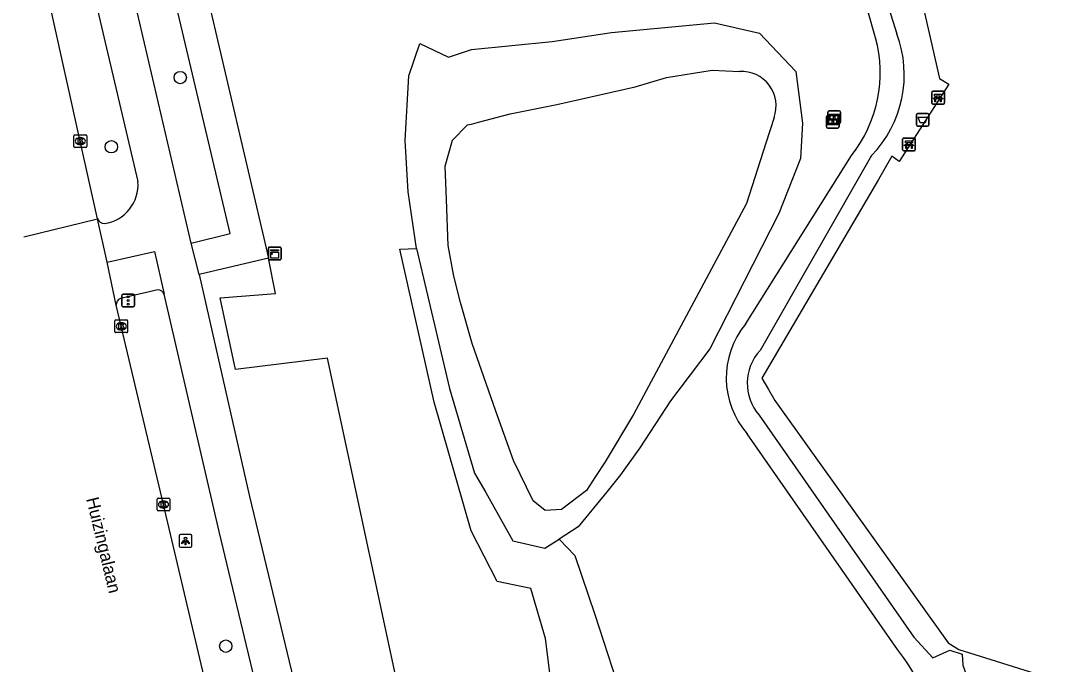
# Model space of a CAD drawing. Extents: x 159451 to 160663, y 388402 to 389723.
# Drawn here: x 159563.1 to 159644.7, y 388629.8 to 388680.5 of the extents above; entities that cross this region are included whole.
import ezdxf

# ---------------------------------------------------------------- set-up
doc = ezdxf.new("R2010")
doc.units = 0
for name, color, linetype in [('IMGEO_Afvalbak', 7, 'Continuous'), ('IMGEO_Bank', 7, 'Continuous'), ('IMGEO_Boom', 7, 'Continuous'), ('IMGEO_Fietspad_gesloten', 7, 'Continuous'), ('IMGEO_Grasland_overig', 7, 'Continuous'), ('IMGEO_Groenvoorziening', 7, 'Continuous'), ('IMGEO_Informatiebord', 7, 'Continuous'), ('IMGEO_Kast', 7, 'Continuous'), ('IMGEO_Kolk', 7, 'Continuous'), ('IMGEO_Lichtpunt', 7, 'Continuous'), ('IMGEO_Meer_plas_ven_vijver', 7, 'Continuous'), ('IMGEO_Openbare_ruimte_label', 7, 'Continuous'), ('IMGEO_Rijbaan_lokaal_halfverhard', 7, 'Continuous'), ('IMGEO_Rijbaan_regionaal_gesloten', 7, 'Continuous'), ('IMGEO_Verkeersregelinstallatiepaal', 7, 'Continuous'), ('IMGEO_Voetpad_open', 7, 'Continuous')]:
    doc.layers.add(name, color=color, linetype=linetype)

msp = doc.modelspace()

# ---------------------------------------------------------------- linework, layer by layer
at = {"layer": 'IMGEO_Afvalbak'}
for p, q in [((159633.667, 388672.309), (159633.667, 388673.109)), ((159633.667, 388673.109), (159633.667, 388672.309)), ((159633.767, 388673.209), (159634.557, 388673.209)), ((159634.557, 388673.209), (159633.767, 388673.209)), ((159634.657, 388673.109), (159634.657, 388672.309)), ((159634.657, 388672.309), (159634.657, 388673.109)), ((159634.557, 388672.209), (159633.767, 388672.209)), ((159633.767, 388672.209), (159634.557, 388672.209))]:
    msp.add_line(p, q, dxfattribs=at)
msp.add_lwpolyline([(159633.81, 388672.923), (159634.514, 388672.923), (159634.365, 388672.453), (159633.959, 388672.453), (159633.81, 388672.923)], dxfattribs=at)
for centre, start, end in [((159633.767, 388673.109), 90, 180), ((159633.767, 388673.109), 90, 180), ((159634.557, 388673.109), 0, 90), ((159634.557, 388673.109), 360, 90), ((159633.767, 388672.309), 180, 270), ((159633.767, 388672.309), 180, 270), ((159634.557, 388672.309), 270, 0), ((159634.557, 388672.309), 270, 0)]:
    msp.add_arc(centre, 0.1, start, end, dxfattribs=at)
at = {"layer": 'IMGEO_Bank'}
for p, q in [((159634.953, 388674.946), (159635.794, 388674.946)), ((159635.794, 388674.946), (159634.953, 388674.946)), ((159634.878, 388674.021), (159634.878, 388674.862)), ((159634.878, 388674.862), (159634.878, 388674.021)), ((159635.575, 388674.344), (159635.182, 388674.344)), ((159635.187, 388674.452), (159635.187, 388674.558)), ((159635.231, 388674.558), (159635.231, 388674.452)), ((159635.519, 388674.564), (159635.237, 388674.564)), ((159635.237, 388674.446), (159635.519, 388674.446)), ((159635.525, 388674.452), (159635.525, 388674.558)), ((159635.569, 388674.558), (159635.569, 388674.452)), ((159635.878, 388674.871), (159635.878, 388674.03)), ((159635.878, 388674.03), (159635.878, 388674.871)), ((159635.803, 388673.946), (159634.962, 388673.946)), ((159634.962, 388673.946), (159635.803, 388673.946)), ((159632.587, 388670.343), (159632.587, 388671.184)), ((159632.587, 388671.184), (159632.587, 388670.343)), ((159632.662, 388671.268), (159633.503, 388671.268)), ((159633.503, 388671.268), (159632.662, 388671.268)), ((159632.896, 388670.774), (159632.896, 388670.88)), ((159632.94, 388670.88), (159632.94, 388670.774)), ((159633.228, 388670.886), (159632.946, 388670.886)), ((159633.234, 388670.774), (159633.234, 388670.88)), ((159633.278, 388670.88), (159633.278, 388670.774)), ((159633.587, 388671.193), (159633.587, 388670.352)), ((159633.587, 388670.352), (159633.587, 388671.193)), ((159633.512, 388670.268), (159632.671, 388670.268)), ((159632.671, 388670.268), (159633.512, 388670.268)), ((159633.284, 388670.666), (159632.891, 388670.666)), ((159632.946, 388670.768), (159633.228, 388670.768))]:
    msp.add_line(p, q, dxfattribs=at)
for points in [[(159635.125, 388674.344), (159634.983, 388674.344), (159635.095, 388674.446), (159635.181, 388674.446)], [(159635.181, 388674.564), (159635.095, 388674.564), (159635.095, 388674.725), (159635.658, 388674.725), (159635.658, 388674.564), (159635.575, 388674.564)], [(159635.175, 388674.337), (159635.175, 388674.13), (159635.132, 388674.13), (159635.132, 388674.337)], [(159635.575, 388674.446), (159635.658, 388674.446), (159635.77, 388674.344), (159635.631, 388674.344)], [(159635.625, 388674.337), (159635.625, 388674.13), (159635.581, 388674.13), (159635.581, 388674.337)], [(159632.89, 388670.886), (159632.804, 388670.886), (159632.804, 388671.047), (159633.367, 388671.047), (159633.367, 388670.886), (159633.284, 388670.886)], [(159632.834, 388670.666), (159632.692, 388670.666), (159632.804, 388670.768), (159632.89, 388670.768)], [(159632.884, 388670.659), (159632.884, 388670.452), (159632.841, 388670.452), (159632.841, 388670.659)], [(159633.284, 388670.768), (159633.367, 388670.768), (159633.479, 388670.666), (159633.34, 388670.666)], [(159633.334, 388670.659), (159633.334, 388670.452), (159633.29, 388670.452), (159633.29, 388670.659)]]:
    msp.add_lwpolyline(points, dxfattribs=at)
for centre, radius, start, end in [((159634.956, 388674.868), 0.0779, 92.4484, 184.28452), ((159634.956, 388674.868), 0.0779, 92.4484, 184.28452), ((159635.8, 388674.868), 0.0779, 2.4484, 94.28452), ((159635.8, 388674.868), 0.0779, 2.4484, 94.28452), ((159635.125, 388674.337), 0.00671, 2.89567, 87.10433), ((159635.182, 388674.337), 0.00671, 92.89567, 177.10433), ((159635.18, 388674.557), 0.00671, 2.89567, 87.10433), ((159635.18, 388674.453), 0.00671, 272.89567, 357.10433), ((159635.237, 388674.557), 0.00671, 92.89567, 177.10433), ((159635.237, 388674.453), 0.00671, 182.89567, 267.10433), ((159635.519, 388674.557), 0.00671, 2.89567, 87.10433), ((159635.519, 388674.453), 0.00671, 272.89567, 357.10433), ((159635.576, 388674.557), 0.00671, 92.89567, 177.10433), ((159635.576, 388674.453), 0.00671, 182.89567, 267.10433), ((159635.574, 388674.337), 0.00671, 2.89567, 87.10433), ((159635.631, 388674.337), 0.00671, 92.89567, 177.10433), ((159634.956, 388674.024), 0.0779, 182.4484, 274.28452), ((159634.956, 388674.024), 0.0779, 182.4484, 274.28452), ((159635.8, 388674.024), 0.0779, 272.4484, 4.28452), ((159635.8, 388674.024), 0.0779, 272.4484, 4.28452), ((159632.665, 388671.19), 0.0779, 92.4484, 184.28452), ((159632.665, 388671.19), 0.0779, 92.4484, 184.28452), ((159632.889, 388670.879), 0.00671, 2.89567, 87.10433), ((159632.946, 388670.879), 0.00671, 92.89567, 177.10433), ((159633.228, 388670.879), 0.00671, 2.89567, 87.10433), ((159633.285, 388670.879), 0.00671, 92.89567, 177.10433), ((159633.509, 388671.19), 0.0779, 2.4484, 94.28452), ((159633.509, 388671.19), 0.0779, 2.4484, 94.28452), ((159632.665, 388670.346), 0.0779, 182.4484, 274.28452), ((159632.665, 388670.346), 0.0779, 182.4484, 274.28452), ((159632.834, 388670.659), 0.00671, 2.89567, 87.10433), ((159632.891, 388670.659), 0.00671, 92.89567, 177.10433), ((159632.889, 388670.775), 0.00671, 272.89567, 357.10433), ((159632.946, 388670.775), 0.00671, 182.89567, 267.10433), ((159633.228, 388670.775), 0.00671, 272.89567, 357.10433), ((159633.285, 388670.775), 0.00671, 182.89567, 267.10433), ((159633.283, 388670.659), 0.00671, 2.89567, 87.10433), ((159633.34, 388670.659), 0.00671, 92.89567, 177.10433), ((159633.509, 388670.346), 0.0779, 272.4484, 4.28452), ((159633.509, 388670.346), 0.0779, 272.4484, 4.28452)]:
    msp.add_arc(centre, radius, start, end, dxfattribs=at)
at = {"layer": 'IMGEO_Boom'}
for centre in [(159575.671, 388676.03), (159570.243, 388670.579), (159579.258, 388631.237)]:
    msp.add_circle(centre, 0.489, dxfattribs=at)
at = {"layer": 'IMGEO_Fietspad_gesloten'}
for points in [[(159576.544, 388662.982), (159568.624, 388696.886)], [(159566.996, 388690.549), (159572.338, 388667.842)], [(159577.172, 388660.52), (159576.544, 388662.982)], [(159569.913, 388661.5), (159573.643, 388662.34), (159574.415, 388658.968)], [(159577.172, 388660.52), (159581.133, 388643.019), (159589.369, 388608.734), (159590.61, 388603.644), (159594.52, 388587.297), (159598.928, 388568.512), (159603.765, 388547.95), (159608.335, 388528.706), (159613.26, 388507.823), (159617.766, 388488.657), (159622.428, 388468.978), (159626.817, 388450.4), (159631.399, 388431.147), (159636.049, 388411.652), (159638.028, 388403.254)], [(159635.066, 388402.93), (159633.14, 388411.125), (159628.643, 388429.97), (159623.96, 388449.846), (159619.346, 388469.16), (159614.917, 388487.946), (159610.308, 388507.337), (159605.503, 388527.843), (159601.008, 388546.724), (159596.625, 388565.41), (159591.677, 388586.33), (159588.042, 388601.633), (159586.471, 388608.09), (159578.73, 388640.269), (159574.415, 388658.968)]]:
    msp.add_lwpolyline(points, dxfattribs=at)
for centre, radius, start, end in [((159569.262, 388667.587), 3.086, 277.89338, 4.73639), ((159569.684, 388665.092), 0.562, 201.15545, 270.21674)]:
    msp.add_arc(centre, radius, start, end, dxfattribs=at)
at = {"layer": 'IMGEO_Grasland_overig'}
msp.add_lwpolyline([(159633.097, 388708.327), (159629.533, 388707.486), (159628.247, 388706.879), (159633.92, 388682.9), (159635.485, 388675.951), (159636.218, 388675.518), (159632.325, 388669.408), (159631.738, 388669.831), (159630.685, 388668.011), (159622.022, 388653.255), (159621.504, 388652.358), (159622.015, 388651.458), (159622.52, 388650.598), (159636.167, 388631.494), (159637.02, 388630.984), (159656.572, 388624.863)], dxfattribs=at)
at = {"layer": 'IMGEO_Groenvoorziening'}
for points in [[(159594.279, 388662.568), (159593.625, 388667.034), (159593.386, 388671.081), (159593.685, 388676.178), (159594.552, 388678.721), (159596.819, 388677.646), (159598.608, 388678.239), (159604.972, 388678.878), (159609.651, 388679.568), (159617.774, 388680.34), (159621.302, 388679.529), (159624.173, 388676.496), (159624.703, 388672.434), (159624.546, 388669.663), (159622.821, 388665.329), (159617.4, 388654.671), (159614.286, 388650.567), (159611.88, 388646.851), (159610.362, 388644.744), (159609.304, 388643.418), (159607.035, 388640.645), (159605.526, 388639.679)], [(159617.133, 388567.112), (159614.295, 388579.867), (159611.298, 388593.777), (159608.357, 388609.407), (159606.398, 388618.373), (159605.048, 388627.034), (159604.46, 388631.854), (159603.293, 388635.791), (159600.643, 388636.335), (159598.603, 388640.324), (159595.684, 388650.454), (159592.966, 388662.518), (159594.279, 388662.568)], [(159594.279, 388662.568), (159596.889, 388651.549), (159598.856, 388644.869), (159599.755, 388643.337), (159601.866, 388639.544), (159604.405, 388638.962), (159605.526, 388639.679)], [(159635.077, 388466.751), (159631.299, 388467.946), (159607.055, 388561.755), (159587.271, 388653.938), (159580.037, 388653.046), (159578.816, 388658.684), (159583.172, 388659.02), (159582.628, 388661.796)], [(159605.526, 388639.679), (159606.749, 388638.389), (159608.339, 388633.739), (159610.052, 388628.478), (159611.363, 388621.757), (159612.902, 388604.641), (159614.422, 388593.149), (159615.567, 388584.134), (159616.974, 388575.645)]]:
    msp.add_lwpolyline(points, dxfattribs=at)
at = {"layer": 'IMGEO_Informatiebord'}
for p, q in [((159626.695, 388672.513), (159626.695, 388673.313)), ((159626.695, 388673.313), (159626.695, 388672.513)), ((159626.795, 388673.413), (159627.585, 388673.413)), ((159627.585, 388673.413), (159626.795, 388673.413)), ((159627.685, 388673.313), (159627.685, 388672.513)), ((159627.685, 388672.513), (159627.685, 388673.313)), ((159626.584, 388672.145), (159626.584, 388672.945)), ((159626.584, 388672.945), (159626.584, 388672.145)), ((159626.684, 388673.045), (159627.474, 388673.045)), ((159627.474, 388673.045), (159626.684, 388673.045)), ((159627.574, 388672.945), (159627.574, 388672.145)), ((159627.574, 388672.145), (159627.574, 388672.945)), ((159627.474, 388672.045), (159626.684, 388672.045)), ((159626.684, 388672.045), (159627.474, 388672.045)), ((159627.585, 388672.413), (159626.795, 388672.413)), ((159626.795, 388672.413), (159627.585, 388672.413))]:
    msp.add_line(p, q, dxfattribs=at)
for points in [[(159626.685, 388672.777), (159627.473, 388672.777), (159627.473, 388672.313), (159626.685, 388672.313), (159626.685, 388672.777)], [(159626.75, 388672.712), (159626.75, 388672.378), (159627.025, 388672.378), (159627.026, 388672.591), (159627.13, 388672.592), (159627.131, 388672.378), (159627.408, 388672.378), (159627.408, 388672.712), (159627.132, 388672.712), (159627.132, 388672.632), (159627.026, 388672.632), (159627.026, 388672.712), (159626.75, 388672.712)], [(159626.796, 388673.145), (159627.584, 388673.145), (159627.584, 388672.681), (159626.796, 388672.681), (159626.796, 388673.145)], [(159626.861, 388673.08), (159626.861, 388672.746), (159627.136, 388672.746), (159627.137, 388672.959), (159627.241, 388672.96), (159627.242, 388672.746), (159627.519, 388672.746), (159627.519, 388673.08), (159627.243, 388673.08), (159627.243, 388673), (159627.137, 388673), (159627.137, 388673.08), (159626.861, 388673.08)]]:
    msp.add_lwpolyline(points, dxfattribs=at)
for centre, start, end in [((159626.795, 388673.313), 90, 180), ((159626.795, 388673.313), 90, 180), ((159627.585, 388673.313), 0, 90), ((159627.585, 388673.313), 360, 90), ((159626.684, 388672.945), 90, 180), ((159626.684, 388672.945), 90, 180), ((159626.795, 388672.513), 180, 270), ((159626.795, 388672.513), 180, 270), ((159627.474, 388672.945), 0, 90), ((159627.474, 388672.945), 360, 90), ((159627.585, 388672.513), 270, 0), ((159627.585, 388672.513), 270, 0), ((159626.684, 388672.145), 180, 270), ((159626.684, 388672.145), 180, 270), ((159627.474, 388672.145), 270, 0), ((159627.474, 388672.145), 270, 0)]:
    msp.add_arc(centre, 0.1, start, end, dxfattribs=at)
at = {"layer": 'IMGEO_Kast'}
for p, q in [((159582.613, 388661.743), (159582.613, 388662.584)), ((159582.613, 388662.584), (159582.613, 388661.743)), ((159582.688, 388662.668), (159583.529, 388662.668)), ((159583.529, 388662.668), (159582.688, 388662.668)), ((159583.613, 388662.593), (159583.613, 388661.752)), ((159583.613, 388661.752), (159583.613, 388662.593)), ((159583.538, 388661.668), (159582.697, 388661.668)), ((159582.697, 388661.668), (159583.538, 388661.668))]:
    msp.add_line(p, q, dxfattribs=at)
for points in [[(159582.808, 388662.458), (159583.408, 388662.458), (159583.408, 388662.373), (159582.808, 388662.373), (159582.808, 388662.458)], [(159582.808, 388662.283), (159583.408, 388662.283), (159583.408, 388661.794), (159582.808, 388661.794), (159582.808, 388662.283)]]:
    msp.add_lwpolyline(points, dxfattribs=at)
msp.add_circle((159582.892, 388662.132), 0.0377, dxfattribs=at)
for centre, start, end in [((159582.691, 388662.59), 92.4484, 184.28452), ((159582.691, 388662.59), 92.4484, 184.28452), ((159583.535, 388662.59), 2.4484, 94.28452), ((159583.535, 388662.59), 2.4484, 94.28452), ((159582.691, 388661.746), 182.4484, 274.28452), ((159582.691, 388661.746), 182.4484, 274.28452), ((159583.535, 388661.746), 272.4484, 4.28452), ((159583.535, 388661.746), 272.4484, 4.28452)]:
    msp.add_arc(centre, 0.0779, start, end, dxfattribs=at)
at = {"layer": 'IMGEO_Kolk'}
for p, q in [((159567.297, 388670.598), (159567.297, 388671.45)), ((159567.372, 388671.524), (159568.224, 388671.524)), ((159567.785, 388671.304), (159567.81, 388671.304)), ((159568.298, 388671.45), (159568.298, 388670.598)), ((159568.224, 388670.524), (159567.372, 388670.524)), ((159567.808, 388670.744), (159567.783, 388670.744)), ((159570.523, 388656.012), (159570.523, 388656.864)), ((159570.598, 388656.938), (159571.45, 388656.938)), ((159571.034, 388656.158), (159571.009, 388656.158)), ((159571.011, 388656.718), (159571.036, 388656.718)), ((159571.524, 388656.864), (159571.524, 388656.012)), ((159571.45, 388655.938), (159570.598, 388655.938)), ((159573.85, 388641.975), (159573.85, 388642.827)), ((159573.925, 388642.901), (159574.777, 388642.901)), ((159574.338, 388642.681), (159574.363, 388642.681)), ((159574.851, 388642.827), (159574.851, 388641.975)), ((159574.777, 388641.901), (159573.925, 388641.901)), ((159574.361, 388642.121), (159574.336, 388642.121))]:
    msp.add_line(p, q, dxfattribs=at)
for points in [[(159567.297, 388670.598), (159567.297, 388671.45)], [(159567.372, 388671.524), (159568.224, 388671.524)], [(159567.618, 388671.224), (159567.741, 388671.224), (159567.741, 388671.073), (159567.871, 388671.224), (159568.035, 388671.224), (159567.889, 388671.073), (159568.042, 388670.824), (159567.89, 388670.824), (159567.805, 388670.988), (159567.741, 388670.921), (159567.741, 388670.824), (159567.618, 388670.824), (159567.618, 388671.224)], [(159568.298, 388671.45), (159568.298, 388670.598)], [(159568.224, 388670.524), (159567.372, 388670.524)], [(159570.523, 388656.012), (159570.523, 388656.864)], [(159570.598, 388656.938), (159571.45, 388656.938)], [(159570.844, 388656.638), (159570.967, 388656.638), (159570.967, 388656.487), (159571.097, 388656.638), (159571.261, 388656.638), (159571.115, 388656.487), (159571.268, 388656.238), (159571.116, 388656.238), (159571.031, 388656.402), (159570.967, 388656.335), (159570.967, 388656.238), (159570.844, 388656.238), (159570.844, 388656.638)], [(159571.524, 388656.864), (159571.524, 388656.012)], [(159571.45, 388655.938), (159570.598, 388655.938)], [(159573.85, 388641.975), (159573.85, 388642.827)], [(159573.925, 388642.901), (159574.777, 388642.901)], [(159574.171, 388642.601), (159574.294, 388642.601), (159574.294, 388642.45), (159574.424, 388642.601), (159574.588, 388642.601), (159574.442, 388642.45), (159574.595, 388642.201), (159574.443, 388642.201), (159574.358, 388642.365), (159574.294, 388642.298), (159574.294, 388642.201), (159574.171, 388642.201), (159574.171, 388642.601)], [(159574.851, 388642.827), (159574.851, 388641.975)], [(159574.777, 388641.901), (159573.925, 388641.901)]]:
    msp.add_lwpolyline(points, dxfattribs=at)
for centre, start, end in [((159567.374, 388671.448), 91.55205, 178.44795), ((159567.374, 388671.448), 91.55205, 178.44795), ((159568.222, 388671.448), 1.55205, 88.44795), ((159568.222, 388671.448), 1.55205, 88.44795), ((159567.374, 388670.6), 181.55205, 268.44795), ((159567.374, 388670.6), 181.55205, 268.44795), ((159568.222, 388670.6), 271.55205, 358.44795), ((159568.222, 388670.6), 271.55205, 358.44795), ((159570.6, 388656.862), 91.55205, 178.44795), ((159570.6, 388656.862), 91.55205, 178.44795), ((159571.448, 388656.862), 1.55205, 88.44795), ((159571.448, 388656.862), 1.55205, 88.44795), ((159570.6, 388656.014), 181.55205, 268.44795), ((159570.6, 388656.014), 181.55205, 268.44795), ((159571.448, 388656.014), 271.55205, 358.44795), ((159571.448, 388656.014), 271.55205, 358.44795), ((159573.927, 388642.825), 91.55205, 178.44795), ((159573.927, 388642.825), 91.55205, 178.44795), ((159574.775, 388642.825), 1.55205, 88.44795), ((159574.775, 388642.825), 1.55205, 88.44795), ((159573.927, 388641.977), 181.55205, 268.44795), ((159573.927, 388641.977), 181.55205, 268.44795), ((159574.775, 388641.977), 271.55205, 358.44795), ((159574.775, 388641.977), 271.55205, 358.44795)]:
    msp.add_arc(centre, 0.0765, start, end, dxfattribs=at)
for centre, major_axis, ratio, start_param, end_param in [((159567.784, 388671.024), (-0.387, 0.002), 0.722429, 4.712389, 7.853982), ((159567.809, 388671.024), (-0.39, 0.002), 0.717154, 1.570796, 4.712389), ((159571.01, 388656.438), (-0.387, 0.002), 0.722429, 4.712389, 7.853982), ((159571.035, 388656.438), (-0.39, 0.002), 0.717154, 1.570796, 4.712389), ((159574.337, 388642.401), (-0.387, 0.002), 0.722429, 4.712389, 7.853982), ((159574.362, 388642.401), (-0.39, 0.002), 0.717154, 1.570796, 4.712389)]:
    msp.add_ellipse(centre, major_axis=major_axis, ratio=ratio, start_param=start_param, end_param=end_param, dxfattribs=at)
at = {"layer": 'IMGEO_Lichtpunt'}
for p, q in [((159575.59, 388639.933), (159575.59, 388639.126)), ((159575.59, 388639.933), (159575.59, 388639.126)), ((159576.492, 388640.028), (159575.684, 388640.028)), ((159576.492, 388640.028), (159575.684, 388640.028)), ((159576.586, 388639.126), (159576.586, 388639.933)), ((159576.586, 388639.126), (159576.586, 388639.933)), ((159575.684, 388639.032), (159576.492, 388639.032)), ((159575.684, 388639.032), (159576.492, 388639.032))]:
    msp.add_line(p, q, dxfattribs=at)
for points in [[(159575.964, 388639.597), (159576.003, 388639.569), (159575.815, 388639.307), (159575.777, 388639.334), (159575.964, 388639.597)], [(159576.066, 388639.549), (159576.113, 388639.549), (159576.113, 388639.227), (159576.066, 388639.227), (159576.066, 388639.549)], [(159576.176, 388639.569), (159576.214, 388639.596), (159576.401, 388639.334), (159576.362, 388639.306), (159576.176, 388639.569)]]:
    msp.add_lwpolyline(points, dxfattribs=at)
msp.add_circle((159576.089, 388639.731), 0.0994, dxfattribs=at)
for centre, start, end in [((159575.684, 388639.933), 90, 180), ((159575.684, 388639.933), 90, 180), ((159576.492, 388639.933), 0, 90), ((159576.492, 388639.933), 0, 90), ((159575.684, 388639.126), 180, 270), ((159575.684, 388639.126), 180, 270), ((159576.492, 388639.126), 270, 0), ((159576.492, 388639.126), 270, 360)]:
    msp.add_arc(centre, 0.0946, start, end, dxfattribs=at)
at = {"layer": 'IMGEO_Meer_plas_ven_vijver'}
for points in [[(159611.526, 388675.288), (159613.969, 388676.024), (159617.586, 388676.613), (159619.739, 388676.506)], [(159622.459, 388672.88), (159621.817, 388670.86), (159620.289, 388666.104), (159611.376, 388649.482), (159609.144, 388645.762), (159608.401, 388644.61), (159607.666, 388643.509), (159605.709, 388642.01), (159604.424, 388641.918), (159603.476, 388642.683), (159601.916, 388645.864), (159600.539, 388649.749), (159598.673, 388655.072), (159597.755, 388658.314), (159597.235, 388660.394), (159596.776, 388662.811), (159596.654, 388666.42), (159596.532, 388669.051), (159597.113, 388671.101), (159598.306, 388672.293), (159598.611, 388672.37), (159599.162, 388672.508), (159601.671, 388673.181), (159605.342, 388673.915), (159611.526, 388675.288)]]:
    msp.add_lwpolyline(points, dxfattribs=at)
msp.add_arc((159619.906, 388673.798), 2.713, 340.21634, 93.53357, dxfattribs=at)
at = {"layer": 'IMGEO_Rijbaan_lokaal_halfverhard'}
for points in [[(159629.735, 388711.632), (159627.628, 388707.506), (159627.72, 388701.259), (159629.111, 388690.285), (159630.725, 388683.916), (159632.123, 388679.482)], [(159630.458, 388679.162), (159629.179, 388683.623), (159628.647, 388685.321), (159628.265, 388686.697), (159627.928, 388688.533), (159627.683, 388689.894), (159625.941, 388700.907), (159625.373, 388703.981), (159623.77, 388710.205)], [(159620.207, 388656.606), (159628.559, 388669.899)], [(159630.133, 388669.88), (159621.358, 388654.539)], [(159621.272, 388649.431), (159633.463, 388631.94), (159634.964, 388630.308), (159636.299, 388630.937), (159637.279, 388630.607), (159637.325, 388629.743), (159637.648, 388628.861), (159639.719, 388628.269), (159651.272, 388625.067), (159653.681, 388624.279), (159656.044, 388623.507)], [(159632.188, 388630.989), (159620.347, 388647.966)]]:
    msp.add_lwpolyline(points, dxfattribs=at)
for centre, radius, start, end in [((159620.281, 388676.422), 10.539, 321.76004, 15.0687), ((159623.616, 388676.238), 9.104, 315.707, 20.87559), ((159625.354, 388652.368), 6.667, 140.5346, 221.32205), ((159624.194, 388651.937), 3.849, 137.46241, 220.60847), ((159615.849, 388618.58), 20.517, 19.35877, 37.21593)]:
    msp.add_arc(centre, radius, start, end, dxfattribs=at)
at = {"layer": 'IMGEO_Rijbaan_regionaal_gesloten'}
for points in [[(159569.16, 388664.889), (159567.798, 388671.024), (159564.462, 388686.08), (159563.101, 388692.202)], [(159563.338, 388663.486), (159569.16, 388664.889)], [(159569.913, 388661.5), (159569.16, 388664.889)], [(159570.633, 388658.101), (159569.913, 388661.5)], [(159631.158, 388402.502), (159629.318, 388410.257), (159624.859, 388429.159), (159620.128, 388449.034), (159615.662, 388467.928), (159611.175, 388486.873), (159606.488, 388506.749), (159601.628, 388527.198), (159597.305, 388545.532), (159592.584, 388565.421), (159587.885, 388585.285), (159584.56, 388599.332), (159582.811, 388606.665), (159581.224, 388613.369), (159577.648, 388628.377), (159574.351, 388642.401), (159571.024, 388656.438), (159570.633, 388658.101)]]:
    msp.add_lwpolyline(points, dxfattribs=at)
at = {"layer": 'IMGEO_Verkeersregelinstallatiepaal'}
for p, q in [((159571.067, 388658.072), (159571.067, 388658.872)), ((159571.067, 388658.872), (159571.067, 388658.072)), ((159571.167, 388658.972), (159571.957, 388658.972)), ((159571.957, 388658.972), (159571.167, 388658.972)), ((159572.057, 388658.872), (159572.057, 388658.072)), ((159572.057, 388658.072), (159572.057, 388658.872)), ((159571.957, 388657.972), (159571.167, 388657.972)), ((159571.167, 388657.972), (159571.957, 388657.972))]:
    msp.add_line(p, q, dxfattribs=at)
for centre in [(159571.562, 388658.762), (159571.562, 388658.472), (159571.562, 388658.182)]:
    msp.add_circle(centre, 0.085, dxfattribs=at)
for centre, start, end in [((159571.167, 388658.872), 90, 180), ((159571.167, 388658.872), 90, 180), ((159571.957, 388658.872), 0, 90), ((159571.957, 388658.872), 360, 90), ((159571.167, 388658.072), 180, 270), ((159571.167, 388658.072), 180, 270), ((159571.957, 388658.072), 270, 0), ((159571.957, 388658.072), 270, 0)]:
    msp.add_arc(centre, 0.1, start, end, dxfattribs=at)
at = {"layer": 'IMGEO_Voetpad_open'}
for points in [[(159574.09, 388698.317), (159582.628, 388661.796)], [(159576.544, 388662.982), (159579.591, 388663.756), (159571.616, 388697.547), (159568.624, 388696.886)], [(159582.628, 388661.796), (159577.172, 388660.52)], [(159573.898, 388659.307), (159570.961, 388658.636)]]:
    msp.add_lwpolyline(points, dxfattribs=at)
for centre, radius, start, end in [((159571.159, 388658.146), 0.528, 112.06059, 184.91581), ((159573.898, 388658.743), 0.564, 23.52553, 89.96828)]:
    msp.add_arc(centre, radius, start, end, dxfattribs=at)

# ---------------------------------------------------------------- texts
at = {"layer": 'IMGEO_Openbare_ruimte_label'}
msp.add_text('Huizingalaan', height=1, rotation=283.59156, dxfattribs=at).set_placement((159568.252, 388642.846))

doc.saveas('drawing.dxf')
